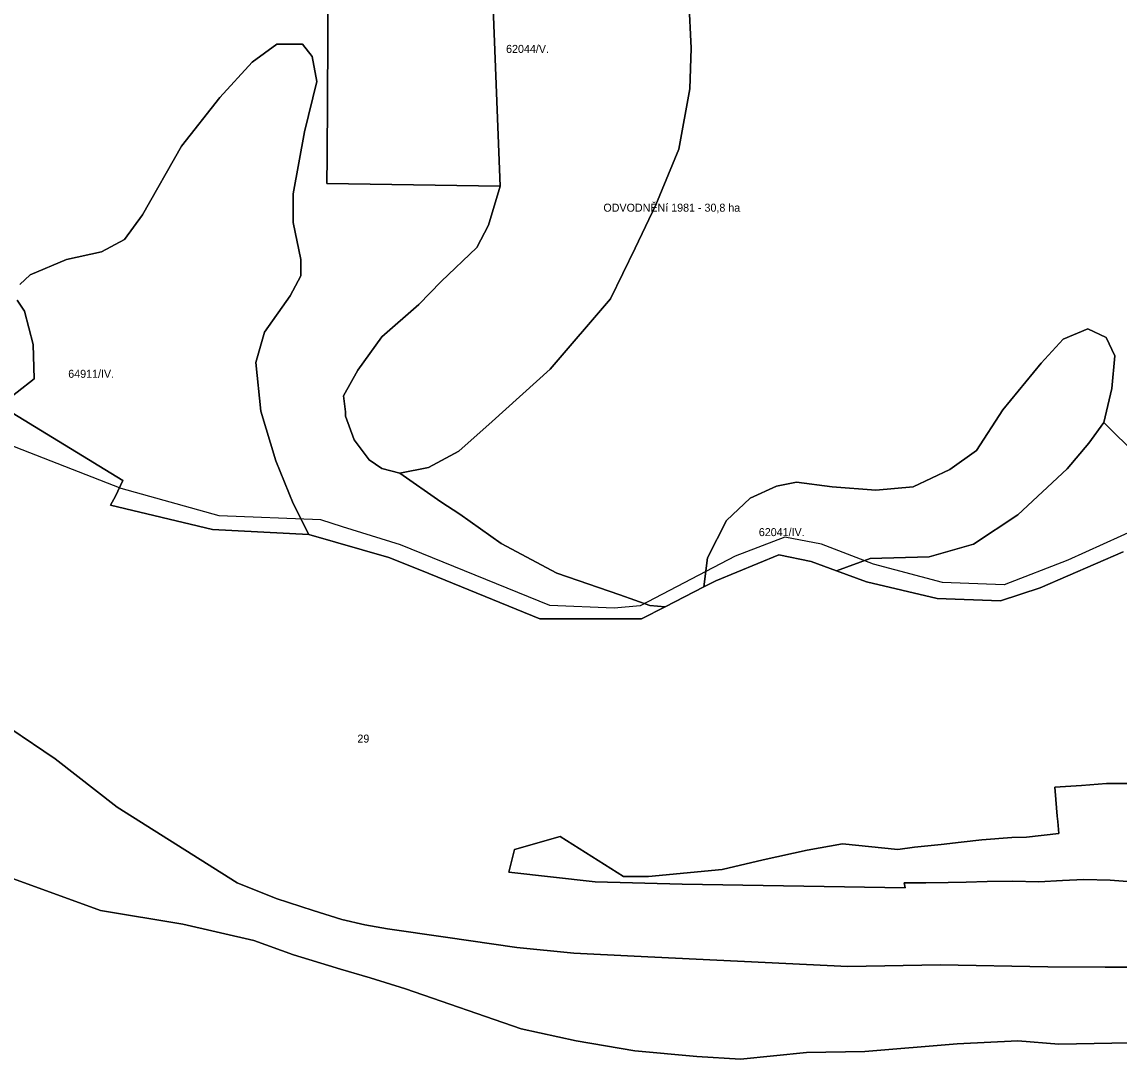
# Model space of a CAD drawing. Extents: x -521621 to -516761, y -1190184 to -1184927.
# Drawn here: x -519813 to -519264, y -1187256 to -1186738 of the extents above; entities that cross this region are included whole.
import ezdxf

# ---------------------------------------------------------------- set-up
doc = ezdxf.new("R2010")
doc.units = 0
doc.layers.add('BPEJ_s', color=7, linetype='Continuous')
doc.layers.add('odvodneni_s', color=7, linetype='Continuous')

msp = doc.modelspace()

# ---------------------------------------------------------------- linework, layer by layer
at = {"layer": 'BPEJ_s'}
for p, q in [((-519823.86, -1186929.63), (-519762.29, -1186966.96)), ((-519762.29, -1186966.96), (-519765.91, -1186974.87)), ((-519765.91, -1186974.87), (-519768.52, -1186979.43)), ((-519768.52, -1186979.43), (-519717.48, -1186991.47)), ((-519717.48, -1186991.47), (-519669.37, -1186994.07)), ((-519669.37, -1186994.07), (-519629.38, -1187005.46)), ((-519303.88, -1187020.75), (-519262.35, -1187002.71)), ((-519629.38, -1187005.46), (-519613.13, -1187011.96)), ((-519465.91, -1187017.11), (-519434.48, -1187004.22)), ((-519434.48, -1187004.22), (-519418.27, -1187007.59)), ((-519418.27, -1187007.59), (-519405.67, -1187012.21)), ((-519613.13, -1187011.96), (-519553.91, -1187036.23)), ((-519405.67, -1187012.21), (-519390.74, -1187017.69)), ((-519471.96, -1187020.22), (-519465.91, -1187017.11)), ((-519390.74, -1187017.69), (-519355.26, -1187025.96)), ((-519491.25, -1187030.12), (-519471.96, -1187020.22)), ((-519323.76, -1187027.18), (-519303.88, -1187020.75)), ((-519503.15, -1187036.23), (-519491.25, -1187030.12)), ((-519355.26, -1187025.96), (-519323.76, -1187027.18)), ((-519553.91, -1187036.23), (-519503.15, -1187036.23)), ((-519796.11, -1187106.16), (-519850.94, -1187069.23)), ((-519765.16, -1187130.37), (-519796.11, -1187106.16)), ((-519270.68, -1187118.4), (-519283.26, -1187119.55)), ((-519258.87, -1187118.4), (-519270.68, -1187118.4)), ((-519283.26, -1187119.55), (-519296.6, -1187120.31)), ((-519296.6, -1187120.31), (-519296.06, -1187126.42)), ((-519296.06, -1187126.42), (-519295.32, -1187134.73)), ((-519705.16, -1187168.1), (-519765.16, -1187130.37)), ((-519295.32, -1187134.73), (-519295.08, -1187137.48)), ((-519295.08, -1187137.48), (-519294.6, -1187143.44)), ((-519543.82, -1187144.89), (-519566.6, -1187151.46)), ((-519512.07, -1187164.93), (-519543.82, -1187144.89)), ((-519318.01, -1187145.48), (-519332.94, -1187146.63)), ((-519310.65, -1187145.36), (-519318.01, -1187145.48)), ((-519294.6, -1187143.44), (-519310.65, -1187145.36)), ((-519402.65, -1187148.64), (-519420.27, -1187151.84)), ((-519375.01, -1187151.44), (-519402.65, -1187148.64)), ((-519366.59, -1187150.24), (-519375.01, -1187151.44)), ((-519353.37, -1187149.04), (-519366.59, -1187150.24)), ((-519343.36, -1187147.83), (-519353.37, -1187149.04)), ((-519332.94, -1187146.63), (-519343.36, -1187147.83)), ((-519566.6, -1187151.46), (-519569.36, -1187162.86)), ((-519442.31, -1187156.65), (-519462.74, -1187161.47)), ((-519420.27, -1187151.84), (-519442.31, -1187156.65)), ((-519462.74, -1187161.47), (-519499.64, -1187164.93)), ((-519569.36, -1187162.86), (-519526.22, -1187167.69)), ((-519526.22, -1187167.69), (-519482.73, -1187168.73)), ((-519499.64, -1187164.93), (-519512.07, -1187164.93)), ((-519349.91, -1187167.88), (-519340.85, -1187167.75)), ((-519340.85, -1187167.75), (-519330.36, -1187167.49)), ((-519330.36, -1187167.49), (-519317.63, -1187167.23)), ((-519317.63, -1187167.23), (-519304.49, -1187167.55)), ((-519304.49, -1187167.55), (-519292.71, -1187167.03)), ((-519292.71, -1187167.03), (-519282.1, -1187166.52)), ((-519282.1, -1187166.52), (-519268.96, -1187166.85)), ((-519268.96, -1187166.85), (-519253.65, -1187167.91)), ((-519685.69, -1187175.9), (-519705.16, -1187168.1)), ((-519482.73, -1187168.73), (-519371.4, -1187170.69)), ((-519371.4, -1187170.69), (-519371.81, -1187168.14)), ((-519371.81, -1187168.14), (-519361.06, -1187168.14)), ((-519361.06, -1187168.14), (-519349.91, -1187167.88)), ((-519667.22, -1187182.03), (-519685.69, -1187175.9)), ((-519652.89, -1187186.47), (-519667.22, -1187182.03)), ((-519641.3, -1187189.2), (-519652.89, -1187186.47)), ((-519629.99, -1187191.18), (-519641.3, -1187189.2)), ((-519601.06, -1187195.24), (-519629.99, -1187191.18)), ((-519565.43, -1187200.37), (-519601.06, -1187195.24)), ((-519536.97, -1187203.2), (-519565.43, -1187200.37)), ((-519506.81, -1187204.71), (-519536.97, -1187203.2)), ((-519400, -1187209.9), (-519506.81, -1187204.71)), ((-519353.85, -1187209.13), (-519400, -1187209.9)), ((-519299.97, -1187210.03), (-519353.85, -1187209.13)), ((-519128.66, -1187211.03), (-519299.97, -1187210.03))]:
    msp.add_line(p, q, dxfattribs=at)
for points in [[(-519579.64, -1186671.38), (-519573.71, -1186819.93), (-519660.41, -1186818.56), (-519660.24, -1186805.39), (-519659.75, -1186717.42)], [(-519479.52, -1186727.04), (-519478.28, -1186750.89), (-519478.9, -1186771.32), (-519484.47, -1186801.36), (-519495.92, -1186829.24), (-519506.3, -1186850.92), (-519518.68, -1186876.17), (-519548.68, -1186911.42), (-519577.72, -1186937.62), (-519594.38, -1186952.39), (-519609.62, -1186960.49), (-519623.9, -1186963.35), (-519632.95, -1186960.96), (-519639.14, -1186956.68), (-519646.75, -1186946.67), (-519651.11, -1186934.89), (-519651.11, -1186932.7), (-519651.99, -1186924.76), (-519644.85, -1186911.9), (-519632.95, -1186895.22), (-519614.38, -1186879.03), (-519603.25, -1186867.56), (-519585.37, -1186850.64), (-519579.62, -1186839.48), (-519573.71, -1186819.93), (-519579.64, -1186671.38)], [(-519659.75, -1186717.42), (-519660.24, -1186805.39), (-519660.41, -1186818.56), (-519573.71, -1186819.93), (-519579.62, -1186839.48), (-519585.37, -1186850.64), (-519603.25, -1186867.56), (-519614.38, -1186879.03), (-519632.95, -1186895.22), (-519644.85, -1186911.9), (-519651.99, -1186924.76), (-519651.11, -1186932.7), (-519651.11, -1186934.89), (-519646.75, -1186946.67), (-519639.14, -1186956.68), (-519632.95, -1186960.96), (-519623.9, -1186963.35), (-519603.43, -1186977.64), (-519593.91, -1186983.83), (-519573.27, -1186998.46), (-519545.47, -1187013.43), (-519513.93, -1187024.13), (-519498.96, -1187029.48), (-519491.25, -1187030.12), (-519503.15, -1187036.23), (-519553.91, -1187036.23), (-519613.13, -1187011.96), (-519629.38, -1187005.46), (-519669.37, -1186994.07), (-519677.22, -1186978.59), (-519685.79, -1186957.15), (-519693.41, -1186932.38), (-519695.79, -1186908.08), (-519691.51, -1186892.84), (-519678.65, -1186874.74), (-519673.41, -1186864.73), (-519673.41, -1186856.64), (-519677.22, -1186838.06), (-519677.22, -1186823.76), (-519671.51, -1186792.8), (-519665.32, -1186767.55), (-519667.7, -1186755.16), (-519672.46, -1186748.97), (-519685.32, -1186748.97), (-519697.7, -1186758.02), (-519713.88, -1186775.65), (-519732.93, -1186799.94), (-519752.45, -1186834.24), (-519761.49, -1186846.63), (-519772.92, -1186852.82), (-519790.54, -1186856.64), (-519808.63, -1186864.26), (-519813.86, -1186869.02)], [(-519255.01, -1186954.79), (-519272.08, -1186938.11), (-519268.11, -1186921.03), (-519266.52, -1186904.74), (-519270.89, -1186895.6), (-519280.02, -1186891.23), (-519292.33, -1186896.4), (-519303.44, -1186908.31), (-519322.5, -1186931.75), (-519335.6, -1186952.01), (-519349.09, -1186961.54), (-519367.36, -1186970.28), (-519386.01, -1186971.87), (-519407.85, -1186970.28), (-519425.71, -1186967.9), (-519435.64, -1186969.89), (-519448.74, -1186975.84), (-519460.65, -1186986.97), (-519470.17, -1187005.64), (-519471.96, -1187020.22), (-519491.25, -1187030.12), (-519498.96, -1187029.48), (-519513.93, -1187024.13), (-519545.47, -1187013.43), (-519573.27, -1186998.46), (-519593.91, -1186983.83), (-519603.43, -1186977.64), (-519623.9, -1186963.35), (-519609.62, -1186960.49), (-519594.38, -1186952.39), (-519577.72, -1186937.62), (-519548.68, -1186911.42), (-519518.68, -1186876.17), (-519506.3, -1186850.92), (-519495.92, -1186829.24), (-519484.47, -1186801.36), (-519478.9, -1186771.32), (-519478.28, -1186750.89), (-519479.52, -1186727.04)], [(-519813.86, -1186869.02), (-519808.63, -1186864.26), (-519790.54, -1186856.64), (-519772.92, -1186852.82), (-519761.49, -1186846.63), (-519752.45, -1186834.24), (-519732.93, -1186799.94), (-519713.88, -1186775.65), (-519697.7, -1186758.02), (-519685.32, -1186748.97), (-519672.46, -1186748.97), (-519667.7, -1186755.16), (-519665.32, -1186767.55), (-519671.51, -1186792.8), (-519677.22, -1186823.76), (-519677.22, -1186838.06), (-519673.41, -1186856.64), (-519673.41, -1186864.73), (-519678.65, -1186874.74), (-519691.51, -1186892.84), (-519695.79, -1186908.08), (-519693.41, -1186932.38), (-519685.79, -1186957.15), (-519677.22, -1186978.59), (-519669.37, -1186994.07), (-519717.48, -1186991.47), (-519768.52, -1186979.43), (-519765.91, -1186974.87), (-519762.29, -1186966.96), (-519823.86, -1186929.63), (-519806.72, -1186916.18), (-519807.2, -1186899.03), (-519811.48, -1186882.36), (-519815.13, -1186876.93)], [(-519815.13, -1186876.93), (-519811.48, -1186882.36), (-519807.2, -1186899.03), (-519806.72, -1186916.18), (-519823.86, -1186929.63)], [(-519262.35, -1187002.71), (-519303.88, -1187020.75), (-519323.76, -1187027.18), (-519355.26, -1187025.96), (-519390.74, -1187017.69), (-519405.67, -1187012.21), (-519388.79, -1187006.03), (-519359.42, -1187005.24), (-519337.18, -1186998.88), (-519314.95, -1186984.19), (-519290.34, -1186961.15), (-519279.62, -1186948.44), (-519272.08, -1186938.11), (-519255.01, -1186954.79)], [(-519850.94, -1187069.23), (-519796.11, -1187106.16), (-519765.16, -1187130.37), (-519705.16, -1187168.1), (-519685.69, -1187175.9), (-519667.22, -1187182.03), (-519652.89, -1187186.47), (-519641.3, -1187189.2), (-519629.99, -1187191.18), (-519601.06, -1187195.24), (-519565.43, -1187200.37), (-519536.97, -1187203.2), (-519506.81, -1187204.71), (-519400, -1187209.9), (-519353.85, -1187209.13), (-519299.97, -1187210.03), (-519128.66, -1187211.03), (-519112.11, -1187210), (-519092.1, -1187208.96), (-519064.5, -1187207.92), (-519024.83, -1187208.61), (-519003.79, -1187209.3), (-518919.06, -1187210.79), (-518913.41, -1187211.72)], [(-519253.65, -1187167.91), (-519268.96, -1187166.85), (-519282.1, -1187166.52), (-519292.71, -1187167.03), (-519304.49, -1187167.55), (-519317.63, -1187167.23), (-519330.36, -1187167.49), (-519340.85, -1187167.75), (-519349.91, -1187167.88), (-519361.06, -1187168.14), (-519371.81, -1187168.14), (-519371.4, -1187170.69), (-519482.73, -1187168.73), (-519526.22, -1187167.69), (-519569.36, -1187162.86), (-519566.6, -1187151.46), (-519543.82, -1187144.89), (-519512.07, -1187164.93), (-519499.64, -1187164.93), (-519462.74, -1187161.47), (-519442.31, -1187156.65), (-519420.27, -1187151.84), (-519402.65, -1187148.64), (-519375.01, -1187151.44), (-519366.59, -1187150.24), (-519353.37, -1187149.04), (-519343.36, -1187147.83), (-519332.94, -1187146.63), (-519318.01, -1187145.48), (-519310.65, -1187145.36), (-519294.6, -1187143.44), (-519295.08, -1187137.48), (-519295.32, -1187134.73), (-519296.06, -1187126.42), (-519296.6, -1187120.31), (-519283.26, -1187119.55), (-519270.68, -1187118.4), (-519258.87, -1187118.4)], [(-519820.61, -1187164.86), (-519773.43, -1187181.96), (-519732.4, -1187188.8), (-519696.84, -1187197.02), (-519677.05, -1187204.06), (-519669.31, -1187206.37), (-519653.61, -1187211.29), (-519638.75, -1187215.67), (-519621.13, -1187221.16), (-519563.24, -1187241.16), (-519535.84, -1187247.13), (-519506.38, -1187252.08), (-519475.48, -1187254.97), (-519453.65, -1187256.21), (-519420.68, -1187252.91), (-519391.43, -1187252.49), (-519345.28, -1187248.58), (-519315, -1187247.13), (-519294.6, -1187248.78), (-519259.17, -1187248.17)], [(-519259.17, -1187248.17), (-519294.6, -1187248.78), (-519315, -1187247.13), (-519345.28, -1187248.58), (-519391.43, -1187252.49), (-519420.68, -1187252.91), (-519453.65, -1187256.21), (-519475.48, -1187254.97), (-519506.38, -1187252.08), (-519535.84, -1187247.13), (-519563.24, -1187241.16), (-519621.13, -1187221.16), (-519638.75, -1187215.67), (-519653.61, -1187211.29), (-519669.31, -1187206.37), (-519677.05, -1187204.06), (-519696.84, -1187197.02), (-519732.4, -1187188.8), (-519773.43, -1187181.96), (-519820.61, -1187164.86)]]:
    msp.add_lwpolyline(points, dxfattribs=at)
msp.add_lwpolyline([(-519471.96, -1187020.22), (-519470.17, -1187005.64), (-519460.65, -1186986.97), (-519448.74, -1186975.84), (-519435.64, -1186969.89), (-519425.71, -1186967.9), (-519407.85, -1186970.28), (-519386.01, -1186971.87), (-519367.36, -1186970.28), (-519349.09, -1186961.54), (-519335.6, -1186952.01), (-519322.5, -1186931.75), (-519303.44, -1186908.31), (-519292.33, -1186896.4), (-519280.02, -1186891.23), (-519270.89, -1186895.6), (-519266.52, -1186904.74), (-519268.11, -1186921.03), (-519272.08, -1186938.11), (-519279.62, -1186948.44), (-519290.34, -1186961.15), (-519314.95, -1186984.19), (-519337.18, -1186998.88), (-519359.42, -1187005.24), (-519388.79, -1187006.03), (-519405.67, -1187012.21), (-519418.27, -1187007.59), (-519434.48, -1187004.22), (-519465.91, -1187017.11)], close=True, dxfattribs=at)
at = {"layer": 'odvodneni_s'}
msp.add_lwpolyline([(-519180.32, -1186653.96), (-519107.8, -1186808), (-519051.05, -1186841.62), (-519178.87, -1186981.02), (-519194.65, -1186976.29), (-519210.41, -1186973.39), (-519237.02, -1186982.89), (-519290.02, -1187006.82), (-519321.89, -1187019.12), (-519352.74, -1187018), (-519387.18, -1187008.83), (-519413.12, -1186998.88), (-519431.46, -1186995.3), (-519456.28, -1187004.92), (-519503.72, -1187029.72), (-519516.77, -1187030.92), (-519548.9, -1187029.52), (-519623.6, -1186999.2), (-519652.51, -1186990.16), (-519663.36, -1186986.75), (-519714.16, -1186984.74), (-519763.11, -1186970.98), (-519841.01, -1186940.74)], dxfattribs=at)

# ---------------------------------------------------------------- texts
at = {"layer": 'BPEJ_s'}
for s, p in [('62044/V.', (-519570.78, -1186753.32)), ('64911/IV.', (-519789.6, -1186915.7)), ('62041/IV.', (-519444.47, -1186994.83)), ('29', (-519645.09, -1187098.03))]:
    msp.add_text(s, height=4, dxfattribs=at).set_placement(p)
at = {"layer": 'odvodneni_s'}
msp.add_text('ODVODNĚNí 1981 - 30,8 ha', height=4, dxfattribs=at).set_placement((-519522.15, -1186832.68))

doc.saveas('drawing.dxf')
